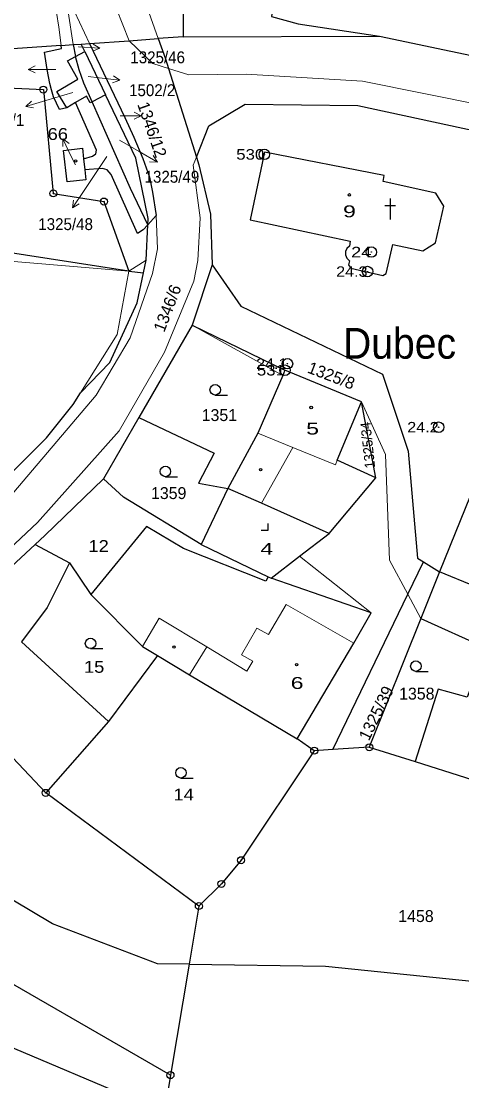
# Model space of a CAD drawing. Extents: x -872229 to -869198, y -1075981 to -1074329.
# Drawn here: x -871098.8 to -871035.9, y -1075369.5 to -1075218 of the extents above; entities that cross this region are included whole.
import ezdxf
from ezdxf.enums import TextEntityAlignment as Align

# ---------------------------------------------------------------- set-up
doc = ezdxf.new("R2010")
doc.units = 0
doc.header["$LTSCALE"] = 0.68
for name, color, linetype, lineweight in [('1', 7, 'Continuous', 25), ('3', 7, 'Continuous', 25), ('4', 7, 'Continuous', 13), ('5', 7, 'Continuous', 25), ('7', 7, 'Continuous', 13), ('8', 7, 'Continuous', 25)]:
    doc.layers.add(name, color=color, linetype=linetype, lineweight=lineweight)
doc.layers.add('2', color=7, linetype='Continuous')

msp = doc.modelspace()

# ---------------------------------------------------------------- linework, layer by layer
at = {"layer": '1'}
for p, q in [((-871090.25, -1075221.28), (-871089.08, -1075221.2)), ((-871089.08, -1075221.2), (-871084.01, -1075231.8)), ((-871093.05, -1075221.91), (-871093.1, -1075221.48)), ((-871089.74, -1075222.36), (-871086.79, -1075228.53)), ((-871088.7, -1075229.54), (-871089.88, -1075226.87)), ((-871083.2, -1075241.94), (-871088.7, -1075229.54)), ((-871073.8, -1075237.43), (-871072.01, -1075232.97)), ((-871089.92, -1075237.67), (-871089.74, -1075239.24)), ((-871080.72, -1075247.11), (-871083.2, -1075241.94)), ((-871083.47, -1075253.75), (-871114.29, -1075249)), ((-871074.38, -1075261.46), (-871082.01, -1075274.66)), ((-871027.67, -1075268.54), (-871039.08, -1075296.69)), ((-871048.15, -1075283.29), (-871050.19, -1075272.43)), ((-871082.01, -1075274.66), (-871087.07, -1075283.41)), ((-871054.81, -1075291.23), (-871048.15, -1075283.29)), ((-871056.96, -1075322.27), (-871059.4, -1075320.6)), ((-871078.37, -1075373.89), (-871149.52, -1075343.97)), ((-871073.44, -1075344.48), (-871074.84, -1075352.78))]:
    msp.add_line(p, q, dxfattribs=at)
for points in [[(-871001.53, -1075179.18), (-871004.71, -1075177.87), (-871056.06, -1075184.2), (-871061.68, -1075207.72), (-871062.03, -1075210.19), (-871063.04, -1075217.35), (-871059.26, -1075218.39), (-871047.62, -1075220.14), (-871017.06, -1075226.57)], [(-871080.85, -1075216.08), (-871075.68, -1075215.86), (-871075.69, -1075220.23), (-871047.62, -1075220.14)], [(-871093.1, -1075221.48), (-871116.67, -1075223.11), (-871132.14, -1075218.66)], [(-871093.1, -1075221.48), (-871091.39, -1075221.36), (-871090.25, -1075221.28)], [(-871091.39, -1075221.36), (-871091.06, -1075223.06), (-871089.74, -1075222.36), (-871090.25, -1075221.28)], [(-871089.08, -1075221.2), (-871083.4, -1075220.8), (-871079.27, -1075220.49)], [(-871075.69, -1075220.23), (-871079.27, -1075220.49), (-871078.22, -1075223.41)], [(-871093.36, -1075230.65), (-871094.19, -1075228.83), (-871094.5, -1075227.84), (-871094.75, -1075226.9), (-871095.12, -1075224.94), (-871095.49, -1075222.43), (-871093.05, -1075221.91)], [(-871092.33, -1075230.38), (-871093.75, -1075228.06), (-871090.73, -1075226.28), (-871092.19, -1075223.66), (-871091.06, -1075223.06)], [(-871089.88, -1075226.87), (-871090.54, -1075224.97), (-871091.06, -1075223.06)], [(-871078.22, -1075223.41), (-871077.79, -1075224.77), (-871073.8, -1075237.43)], [(-871132.62, -1075226.11), (-871114.29, -1075226.93), (-871095.65, -1075227.79), (-871094.24, -1075242.63), (-871087.01, -1075243.79), (-871083.47, -1075253.75), (-871081.37, -1075254)], [(-871088.7, -1075229.54), (-871088.95, -1075229.67), (-871089.52, -1075228.73), (-871091.05, -1075229.63)], [(-871082.45, -1075237.6), (-871086.79, -1075228.53), (-871088.7, -1075229.54)], [(-871089.92, -1075237.67), (-871088.65, -1075237.32), (-871088.18, -1075236.96), (-871088.06, -1075236.44), (-871091.05, -1075229.63), (-871092.33, -1075230.38), (-871093.36, -1075230.65)], [(-871072.01, -1075232.97), (-871066.83, -1075229.86), (-871050.73, -1075230.05), (-871024.91, -1075235.65), (-871004.91, -1075242.17), (-870984.75, -1075250.58), (-870962.8, -1075257.63), (-870944.86, -1075263.23), (-870926.98, -1075271.99), (-870918.87, -1075275.55), (-870910.63, -1075280.9)], [(-871084.01, -1075231.8), (-871082.74, -1075234.58), (-871081.43, -1075237.66), (-871080.49, -1075240.33), (-871080.05, -1075242.43), (-871079.54, -1075245.79), (-871080.72, -1075247.11)], [(-871089.74, -1075239.24), (-871089.57, -1075240.67), (-871092.27, -1075240.99), (-871092.79, -1075236.48), (-871090.09, -1075236.16), (-871089.92, -1075237.67)], [(-871080.72, -1075247.11), (-871080.67, -1075246.21), (-871082.45, -1075237.6)], [(-871073.8, -1075237.43), (-871073.45, -1075238.54), (-871071.78, -1075245.58), (-871071.55, -1075252.85)], [(-871080.72, -1075247.11), (-871081.4, -1075247.82), (-871082.22, -1075248.38), (-871085.96, -1075239.92), (-871086.55, -1075239.25), (-871087.22, -1075239.05), (-871089.74, -1075239.24)], [(-871081.37, -1075254), (-871080.98, -1075252.18), (-871080.72, -1075247.11)], [(-871071.55, -1075252.85), (-871074.38, -1075261.46), (-871061.14, -1075267.9)], [(-871071.55, -1075252.85), (-871067.46, -1075258.72), (-871047.21, -1075268.46), (-871043.52, -1075279.47), (-871042.22, -1075294.74), (-871041.36, -1075295.27), (-871039.08, -1075296.69)], [(-871091.41, -1075272.82), (-871090.35, -1075271.13), (-871086.17, -1075266.8), (-871082.28, -1075258.28), (-871081.37, -1075254)], [(-871061.14, -1075267.9), (-871061.46, -1075268.64), (-871065.01, -1075276.88), (-871069.29, -1075284.78)], [(-871048.15, -1075283.29), (-871053.66, -1075280.73), (-871050.19, -1075272.43), (-871061.14, -1075267.9)], [(-871119.87, -1075302.18), (-871112.61, -1075295.91), (-871109.75, -1075292.07), (-871095.22, -1075277.55), (-871091.41, -1075272.82)], [(-871082.01, -1075274.66), (-871071.25, -1075279.76), (-871073.47, -1075284.05), (-871069.29, -1075284.78)], [(-871087.07, -1075283.41), (-871095.43, -1075291.53), (-871096.84, -1075292.82), (-871091.92, -1075295.42), (-871088.88, -1075299.94)], [(-871073.1, -1075292.79), (-871084.21, -1075286.02), (-871087.07, -1075283.41)], [(-871069.29, -1075284.78), (-871073.1, -1075292.79), (-871063.52, -1075297.41), (-871063.11, -1075297.61)], [(-871054.81, -1075291.23), (-871064.49, -1075286.92), (-871069.29, -1075284.78)], [(-871063.52, -1075297.41), (-871063.87, -1075298.04), (-871075.62, -1075293.36), (-871080.94, -1075290.22), (-871088.88, -1075299.94), (-871081.48, -1075307.38), (-871079.33, -1075308.68)], [(-871063.11, -1075297.61), (-871059.04, -1075294.48), (-871054.81, -1075291.23)], [(-871096.84, -1075292.82), (-871102.97, -1075298.45), (-871113.42, -1075309.13)], [(-871091.92, -1075295.42), (-871095.1, -1075301.79), (-871098.8, -1075306.71), (-871086.34, -1075318.08)], [(-871054.29, -1075322.1), (-871043.59, -1075299.91), (-871041.36, -1075295.27)], [(-871028.88, -1075300.9), (-871039.08, -1075296.69), (-871041.74, -1075303.38)], [(-871059.4, -1075320.6), (-871051.32, -1075306.91), (-871048.84, -1075302.56), (-871063.11, -1075297.61)], [(-871041.74, -1075303.38), (-871049.09, -1075321.78), (-871042.54, -1075323.84)], [(-871041.74, -1075303.38), (-871032.46, -1075307.57), (-871035.1, -1075314.6), (-871039.25, -1075313.47), (-871042.54, -1075323.84), (-871028.14, -1075328.37)], [(-871073.44, -1075344.48), (-871095.32, -1075328.3), (-871113.42, -1075309.13)], [(-871079.33, -1075308.68), (-871086.34, -1075318.08), (-871095.32, -1075328.3)], [(-871079.33, -1075308.68), (-871074.79, -1075311.44), (-871059.4, -1075320.6)], [(-871056.96, -1075322.27), (-871067.41, -1075337.92), (-871070.22, -1075341.31), (-871073.44, -1075344.48)], [(-871049.09, -1075321.78), (-871054.29, -1075322.1), (-871056.96, -1075322.27)], [(-871074.84, -1075352.78), (-871079.33, -1075352.72), (-871094.35, -1075347.04), (-871130.43, -1075325.54)], [(-871077.5, -1075368.64), (-871138.58, -1075333.41), (-871149.52, -1075343.97)], [(-871074.84, -1075352.78), (-871077.5, -1075368.64), (-871078.37, -1075373.89), (-871082.62, -1075399.25), (-871029.72, -1075411.9)], [(-871074.84, -1075352.78), (-871055.34, -1075353.05), (-871020.46, -1075356.63)]]:
    msp.add_lwpolyline(points, dxfattribs=at)
msp.add_lwpolyline([(-871052.29, -1075250.48), (-871052.48, -1075250.92), (-871052.49, -1075251.42), (-871052.28, -1075251.89), (-871051.9, -1075252.25), (-871052.04, -1075252.84), (-871051.73, -1075253.31), (-871051.11, -1075253.46), (-871047.17, -1075254.38), (-871046.7, -1075254.08), (-871045.71, -1075249.91), (-871041.46, -1075250.82), (-871039.64, -1075249.67), (-871038.46, -1075244.43), (-871039.6, -1075242.6), (-871047.13, -1075240.93), (-871046.96, -1075240.09), (-871064.05, -1075236.72), (-871066.09, -1075246.41), (-871051.8, -1075249.47), (-871051.94, -1075250.15)], close=True, dxfattribs=at)
at = {"layer": '3'}
for p, q in [((-871071.103, -1075271.45), (-871069.353, -1075271.45)), ((-871078.223, -1075283.12), (-871076.473, -1075283.12)), ((-871088.923, -1075307.69), (-871087.173, -1075307.69)), ((-871042.433, -1075310.94), (-871040.683, -1075310.94)), ((-871076.003, -1075326.18), (-871074.253, -1075326.18))]:
    msp.add_line(p, q, dxfattribs=at)
msp.add_lwpolyline([(-871064.521, -1075290.78), (-871063.52, -1075290.78), (-871063.52, -1075289.78)], dxfattribs=at)
for centre in [(-871071.1029, -1075270.6998), (-871078.2229, -1075282.3698), (-871088.9229, -1075306.9398), (-871042.4329, -1075310.1898), (-871076.0029, -1075325.4298)]:
    msp.add_circle(centre, 0.75, dxfattribs=at)
at = {"layer": '4'}
for p, q in [((-871093.8, -1075216.76), (-871093.43, -1075218.88)), ((-871092.1, -1075216.66), (-871091.39, -1075221.36)), ((-871091.2, -1075216.61), (-871089.08, -1075221.2)), ((-871085.21, -1075216.27), (-871083.4, -1075220.8)), ((-871080.85, -1075216.08), (-871079.27, -1075220.49)), ((-871093.43, -1075218.88), (-871093.1, -1075221.48)), ((-871083.4, -1075220.8), (-871080.01, -1075224.08)), ((-871080.01, -1075224.08), (-871077.79, -1075224.77)), ((-871066.66, -1075225.6), (-871050.04, -1075226.59)), ((-871050.04, -1075226.59), (-871024.09, -1075231.8)), ((-871074.27, -1075238.6), (-871073.8, -1075237.43)), ((-871074.27, -1075238.6), (-871073.26, -1075246.1)), ((-871079.54, -1075245.79), (-871079.34, -1075250.53)), ((-871080.08, -1075254.08), (-871079.34, -1075250.53)), ((-871102.8, -1075252.13), (-871083.47, -1075253.75)), ((-871083.47, -1075253.75), (-871080.98, -1075252.18)), ((-871085.12, -1075262.8), (-871083.47, -1075253.75)), ((-871083.24, -1075263.25), (-871080.08, -1075254.08)), ((-871078.36, -1075265.32), (-871074.18, -1075255.16)), ((-871074.38, -1075261.46), (-871061.46, -1075268.64)), ((-871090.35, -1075271.13), (-871085.12, -1075262.8)), ((-871088.11, -1075271.44), (-871083.24, -1075263.25)), ((-871084.85, -1075276.56), (-871078.36, -1075265.32)), ((-871100.71, -1075286.26), (-871088.11, -1075271.44)), ((-871050.19, -1075272.43), (-871046.76, -1075279.93)), ((-871096.49, -1075289.67), (-871084.85, -1075276.56)), ((-871065.01, -1075276.88), (-871060.03, -1075278.95)), ((-871064.49, -1075286.92), (-871060.03, -1075278.95)), ((-871060.03, -1075278.95), (-871053.94, -1075281.41)), ((-871053.94, -1075281.41), (-871053.66, -1075280.73)), ((-871115.21, -1075307.2), (-871096.49, -1075289.67)), ((-871059.04, -1075294.48), (-871048.84, -1075302.56)), ((-871081.48, -1075307.38), (-871079.11, -1075303.35)), ((-871079.11, -1075303.35), (-871072.32, -1075307.44)), ((-871067.33, -1075308.58), (-871065.15, -1075304.76)), ((-871065.15, -1075304.76), (-871063.47, -1075305.69)), ((-871074.79, -1075311.44), (-871072.32, -1075307.44)), ((-871072.32, -1075307.44), (-871066.57, -1075310.89)), ((-871067.33, -1075308.58), (-871065.73, -1075309.46)), ((-871066.57, -1075310.89), (-871065.73, -1075309.46))]:
    msp.add_line(p, q, dxfattribs=at)
for points in [[(-871077.79, -1075224.77), (-871074.86, -1075225.68), (-871066.66, -1075225.6)], [(-871074.18, -1075255.16), (-871073.59, -1075252.24), (-871073.26, -1075246.1)], [(-871046.76, -1075279.93), (-871046.19, -1075295.03), (-871043.59, -1075299.91), (-871041.74, -1075303.38)], [(-871063.47, -1075305.69), (-871060.98, -1075301.4), (-871051.32, -1075306.91)]]:
    msp.add_lwpolyline(points, dxfattribs=at)
at = {"layer": '5'}
for p, q in [((-871046.11, -1075243.37), (-871046.11, -1075246.37)), ((-871046.861, -1075244.371), (-871045.359, -1075244.371))]:
    msp.add_line(p, q, dxfattribs=at)
for centre in [(-871091.0468, -1075237.9892), (-871051.9368, -1075242.8392), (-871057.3968, -1075273.2292), (-871064.6168, -1075282.0992), (-871076.9968, -1075307.4592), (-871059.4768, -1075309.9892)]:
    msp.add_circle(centre, 0.175, dxfattribs=at)
at = {"layer": '7'}
for p, q in [((-871087.583, -1075221.857), (-871088.557, -1075221.305)), ((-871090.58, -1075221.7), (-871090.62, -1075221.7)), ((-871097.831, -1075224.91), (-871096.83, -1075225.411)), ((-871094.83, -1075224.91), (-871093.88, -1075224.91)), ((-871084.721, -1075226.456), (-871085.654, -1075225.837)), ((-871098.16, -1075230.227), (-871097.056, -1075230.413)), ((-871081.689, -1075231.54), (-871082.69, -1075231.039)), ((-871092.886, -1075234.823), (-871092.897, -1075235.942)), ((-871079.371, -1075238.16), (-871079.988, -1075237.226)), ((-871091.508, -1075244.688), (-871090.533, -1075244.138))]:
    msp.add_line(p, q, dxfattribs=at)
for points in [[(-871090.58, -1075221.7), (-871087.583, -1075221.857), (-871088.609, -1075222.305)], [(-871094.83, -1075224.91), (-871097.831, -1075224.91), (-871096.83, -1075224.409)], [(-871089.26, -1075225.9), (-871087.7, -1075226.09), (-871084.721, -1075226.456), (-871085.776, -1075226.831)], [(-871091.45, -1075228.19), (-871095.29, -1075229.35), (-871098.16, -1075230.227), (-871097.349, -1075229.456)], [(-871084.69, -1075231.54), (-871081.689, -1075231.54), (-871082.69, -1075232.041)], [(-871091.09, -1075238.53), (-871091.57, -1075237.52), (-871092.886, -1075234.823), (-871091.996, -1075235.503)], [(-871084.78, -1075235.02), (-871081.97, -1075236.66), (-871079.371, -1075238.16), (-871080.489, -1075238.093)], [(-871086.61, -1075237.36), (-871089.83, -1075242.2), (-871091.508, -1075244.688), (-871091.363, -1075243.578)]]:
    msp.add_lwpolyline(points, dxfattribs=at)
at = {"layer": '8'}
for centre, radius in [((-871095.65, -1075227.7899), 0.5), ((-871095.65, -1075227.7899), 0.0303), ((-871064.09, -1075237.0498), 0.75), ((-871064.09, -1075237.0498), 0.03), ((-871094.24, -1075242.6299), 0.5), ((-871094.24, -1075242.6299), 0.0303), ((-871087.01, -1075243.7899), 0.5), ((-871087.01, -1075243.7899), 0.0303), ((-871048.79, -1075251.0098), 0.75), ((-871048.79, -1075251.0098), 0.03), ((-871049.34, -1075253.7998), 0.75), ((-871049.34, -1075253.7998), 0.03), ((-871060.78, -1075266.9698), 0.75), ((-871061.14, -1075267.8998), 0.75), ((-871061.14, -1075267.8998), 0.03), ((-871060.78, -1075266.9698), 0.03), ((-871039.18, -1075276.0398), 0.75), ((-871039.18, -1075276.0398), 0.03), ((-871049.09, -1075321.7799), 0.5), ((-871056.96, -1075322.2699), 0.5), ((-871056.96, -1075322.2699), 0.0303), ((-871049.09, -1075321.7799), 0.0303), ((-871095.32, -1075328.2999), 0.5), ((-871095.32, -1075328.2999), 0.0303), ((-871067.41, -1075337.9199), 0.5), ((-871067.41, -1075337.9199), 0.0303), ((-871070.22, -1075341.3099), 0.5), ((-871070.22, -1075341.3099), 0.0303), ((-871073.44, -1075344.4799), 0.5), ((-871073.44, -1075344.4799), 0.0303), ((-871077.5, -1075368.6399), 0.5), ((-871077.5, -1075368.6399), 0.0303)]:
    msp.add_circle(centre, radius, dxfattribs=at)

# ---------------------------------------------------------------- texts
at = {"layer": '2'}
for s, width, p in [('1325/46', 0.95, (-871079.33, -1075224.03)), ('1502/2', 0.95, (-871080.109, -1075228.73)), ('1502/1', 0.95, (-871101.679, -1075232.99)), ('66', 1.15, (-871093.6, -1075234.99)), ('1325/49', 0.95, (-871077.29, -1075241.1)), ('1325/48', 0.95, (-871092.48, -1075247.87))]:
    msp.add_text(s, height=1.7, dxfattribs=dict(at, width=width)).set_placement(p, align=Align.CENTER)
msp.add_text('1346/12', height=1.7, rotation=289, dxfattribs=at).set_placement((-871080.9198, -1075233.7808), align=Align.CENTER)
for s, width, p in [('9', 1.45, (-871052.84, -1075246.04)), ('5', 1.45, (-871058.11, -1075277.09)), ('12', 1.15, (-871089.22, -1075293.88)), ('4', 1.45, (-871064.66, -1075294.28)), ('15', 1.15, (-871089.86, -1075311.14)), ('6', 1.45, (-871060.32, -1075313.45)), ('14', 1.15, (-871077.07, -1075329.39))]:
    msp.add_text(s, height=1.7, dxfattribs=dict(at, width=width)).set_placement(p)
for s, rotation, p in [('1346/6', 69, (-871078.396, -1075262.584)), ('1325/8', 339, (-871058.054, -1075268.203)), ('1325/39', 64, (-871049.146, -1075320.972))]:
    msp.add_text(s, height=1.7, rotation=rotation, dxfattribs=at).set_placement(p)
for s, p in [('1351', (-871073.04, -1075275.16)), ('1359', (-871080.28, -1075286.31)), ('1358', (-871044.83, -1075314.97)), ('1458', (-871044.95, -1075346.76))]:
    msp.add_text(s, height=1.7, dxfattribs=at).set_placement(p)
at = {"layer": '2', "width": 0.95}
msp.add_text('1325/34', height=1.445, rotation=96, dxfattribs=at).set_placement((-871048.251, -1075281.834))
at = {"layer": '7', "width": 0.95}
msp.add_text('Dubec', height=4.4, dxfattribs=at).set_placement((-871044.769, -1075266.25), align=Align.CENTER)
at = {"layer": '8'}
for s, width, p in [('530', 1.2, (-871064.09, -1075237.8)), ('24', 1.3, (-871048.789, -1075251.76)), ('24.3', 1.15, (-871049.34, -1075254.55)), ('24.1', 1.15, (-871060.78, -1075267.72)), ('531', 1.2, (-871061.14, -1075268.65)), ('24.2', 1.15, (-871039.18, -1075276.79))]:
    msp.add_text(s, height=1.5, dxfattribs=dict(at, width=width)).set_placement(p, align=Align.RIGHT)

doc.saveas('drawing.dxf')
